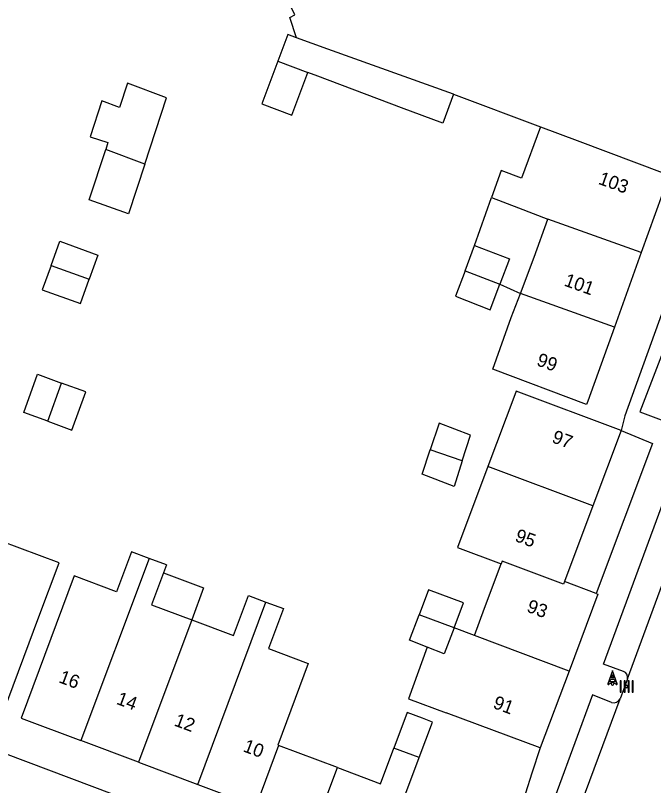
# Model space of a CAD drawing. Extents: x 192664 to 192925, y 446334 to 446521.
# Drawn here: x 192789.9 to 192837.8, y 446395.7 to 446453.5 of the extents above; entities that cross this region are included whole.
import ezdxf

# ---------------------------------------------------------------- set-up
doc = ezdxf.new("R2010")
doc.units = 0
for name, color, linetype in [('( Toegevoegd 29-11-2021 14_41_42) wegdeel vlak', 7, 'Continuous'), ('B-GV-KG-GRENS_WERKGRENS-G', 7, 'Continuous'), ('bovenleidingmast', 7, 'Continuous'), ('huisnummerreeks BGT', 7, 'Continuous'), ('kant open verharding', 7, 'Continuous'), ('kant verharding', 7, 'Continuous'), ('kolk', 7, 'Continuous'), ('Luifel', 7, 'Continuous'), ('pand op maaiveld vlak', 7, 'Continuous')]:
    doc.layers.add(name, color=color, linetype=linetype)

msp = doc.modelspace()

# ---------------------------------------------------------------- linework, layer by layer
at = {"layer": '( Toegevoegd 29-11-2021 14_41_42) wegdeel vlak'}
msp.add_lwpolyline([(192807.071, 446391.618), (192806.989, 446391.38), (192789.199, 446398.084), (192788.212, 446398.449), (192770.35, 446405.075), (192770.467, 446405.283)], dxfattribs=at)
at = {"layer": 'B-GV-KG-GRENS_WERKGRENS-G'}
msp.add_lwpolyline([(192845.78, 446436.459), (192844.328, 446436.785), (192842.142, 446437.586), (192836.819, 446423.746), (192840.619, 446422.317)], close=True, dxfattribs=at)
at = {"layer": 'bovenleidingmast'}
for p, q in [((192834.756, 446404.322), (192834.415, 446403.349)), ((192835.115, 446403.349), (192834.774, 446404.322))]:
    msp.add_line(p, q, dxfattribs=at)
msp.add_lwpolyline([(192834.887, 446403.699), (192834.957, 446403.499), (192834.573, 446403.499), (192834.643, 446403.699)], close=True, dxfattribs=at)
for points in [[(192834.774, 446404.019), (192834.852, 446403.799), (192834.678, 446403.799), (192834.756, 446404.019)], [(192834.509, 446403.316), (192834.538, 446403.399), (192834.678, 446403.399)], [(192834.852, 446403.399), (192834.992, 446403.399), (192835.021, 446403.316)]]:
    msp.add_lwpolyline(points, dxfattribs=at)
for centre, radius, start, end in [((192834.765, 446404.319), 0.01, 19.29005, 160.70995), ((192834.765, 446404.016), 0.01, 19.29005, 160.70995), ((192834.462, 446403.332), 0.05, 160.70995, 340.70995), ((192834.765, 446403.349), 0.1, 0, 180), ((192834.765, 446403.349), 0.1, 180, 0), ((192834.765, 446403.349), 0.1, 30, 150), ((192835.068, 446403.332), 0.05, 199.29005, 19.29005)]:
    msp.add_arc(centre, radius, start, end, dxfattribs=at)
at = {"layer": 'kant open verharding'}
for points in [[(192846.946, 446454.816), (192845.635, 446451.129), (192845.293, 446450.169), (192841.851, 446440.492), (192835.693, 446423.446), (192835.401, 446422.35)], [(192835.401, 446422.35), (192837.776, 446421.364), (192833.548, 446410.11)], [(192829.343, 446398.525), (192828.71, 446396.639), (192827.284, 446392.126)]]:
    msp.add_lwpolyline(points, dxfattribs=at)
at = {"layer": 'kant verharding'}
for p, q in [((192835.879, 446403.721), (192847.824, 446436.149)), ((192835.879, 446403.721), (192835.348, 446402.2)), ((192828.852, 446384.771), (192835.348, 446402.2))]:
    msp.add_line(p, q, dxfattribs=at)
for points in [[(192835.578, 446404.274), (192834.092, 446404.819), (192845.78, 446436.459), (192847.207, 446435.879)], [(192834.695, 446401.945), (192833.274, 446402.505), (192826.627, 446384.5)]]:
    msp.add_lwpolyline(points, dxfattribs=at)
for centre, radius, start, end in [((192835.451, 446403.846), 0.446, 343.69235, 73.42689), ((192834.859, 446402.489), 0.568, 253.24629, 329.41554)]:
    msp.add_arc(centre, radius, start, end, dxfattribs=at)
at = {"layer": 'kolk'}
for points in [[(192835.425, 446403.128), (192835.425, 446403.553), (192835.34, 446403.553), (192835.34, 446403.128), (192835.34, 446402.703), (192835.425, 446402.703)], [(192835.723, 446403.128), (192835.723, 446403.553), (192835.638, 446403.553), (192835.638, 446403.128), (192835.638, 446402.703), (192835.723, 446402.703)], [(192836.02, 446403.128), (192836.02, 446403.553), (192835.935, 446403.553), (192835.935, 446403.128), (192835.935, 446402.703), (192836.02, 446402.703)], [(192836.318, 446403.128), (192836.318, 446403.553), (192836.233, 446403.553), (192836.233, 446403.128), (192836.233, 446402.703), (192836.318, 446402.703)]]:
    msp.add_lwpolyline(points, close=True, dxfattribs=at)
for start, end in [(0, 180), (180, 0)]:
    msp.add_arc((192835.829, 446403.128), 0.1, start, end, dxfattribs=at)
at = {"layer": 'Luifel'}
for p, q in [((192824.406, 446436.208), (192825.677, 446439.814)), ((192826.303, 446433.31), (192827.856, 446432.619))]:
    msp.add_line(p, q, dxfattribs=at)
for points in [[(192809.636, 446450.044), (192808.434, 446446.847), (192810.703, 446445.994), (192811.905, 446449.19)], [(192801.06, 446411.669), (192804.079, 446410.539), (192803.18, 446408.138)]]:
    msp.add_lwpolyline(points, dxfattribs=at)
at = {"layer": 'pand op maaiveld vlak'}
for p, q in [((192809.636, 446450.044), (192811.905, 446449.19)), ((192822.832, 446447.565), (192829.348, 446445.115)), ((192799.655, 446442.322), (192796.727, 446443.426)), ((192836.921, 446435.689), (192829.917, 446438.195)), ((192823.695, 446434.314), (192824.406, 446436.208)), ((192836.921, 446435.689), (192834.902, 446430.082)), ((192792.626, 446434.715), (192795.486, 446433.679)), ((192823.695, 446434.314), (192826.303, 446433.31)), ((192834.902, 446430.082), (192827.856, 446432.619)), ((192792.379, 446423.035), (192793.415, 446425.895)), ((192835.401, 446422.35), (192833.275, 446416.68)), ((192823.485, 446420.072), (192821.091, 446420.878)), ((192833.275, 446416.68), (192825.41, 446419.628)), ((192833.275, 446416.68), (192831.149, 446411.009)), ((192799.989, 446412.75), (192794.873, 446399.08)), ((192801.283, 446412.266), (192799.989, 446412.75)), ((192801.283, 446412.266), (192801.06, 446411.669)), ((192833.548, 446410.11), (192831.149, 446411.009)), ((192803.639, 446395.798), (192808.756, 446409.467)), ((192803.18, 446408.138), (192799.184, 446397.466)), ((192822.87, 446407.533), (192820.248, 446408.501)), ((192824.402, 446406.959), (192822.87, 446407.533)), ((192831.506, 446404.294), (192824.402, 446406.959)), ((192831.506, 446404.294), (192829.343, 446398.525)), ((192829.343, 446398.525), (192822.281, 446401.173)), ((192799.184, 446397.466), (192794.873, 446399.08)), ((192809.693, 446398.714), (192807.995, 446394.168)), ((192814.113, 446397.059), (192809.693, 446398.714)), ((192820.25, 446397.804), (192818.344, 446398.518)), ((192819.25, 446395.133), (192820.25, 446397.804)), ((192799.184, 446397.466), (192803.639, 446395.798)), ((192811.461, 446389.974), (192814.113, 446397.059)), ((192803.639, 446395.798), (192807.995, 446394.168))]:
    msp.add_line(p, q, dxfattribs=at)
for points in [[(192811.054, 446451.801), (192810.545, 446453.32), (192810.916, 446453.523), (192809.437, 446456.628), (192809.575, 446456.694), (192822.797, 446462.99)], [(192811.054, 446451.801), (192810.39, 446452.051), (192809.636, 446450.044)], [(192822.832, 446447.565), (192813.388, 446450.95), (192811.054, 446451.801)], [(192822.832, 446447.565), (192822.026, 446445.384), (192818.939, 446446.545), (192812.653, 446448.909), (192811.905, 446449.19)], [(192799.655, 446442.322), (192801.281, 446447.288), (192798.356, 446448.4), (192797.756, 446446.568), (192796.436, 446447.059), (192795.568, 446444.366), (192796.895, 446443.939), (192796.727, 446443.426)], [(192829.348, 446445.115), (192827.942, 446441.255), (192826.414, 446441.835), (192825.677, 446439.814)], [(192829.348, 446445.115), (192832.102, 446444.08), (192838.693, 446441.612)], [(192799.655, 446442.322), (192798.431, 446438.581), (192795.483, 446439.628), (192796.727, 446443.426)], [(192838.693, 446441.612), (192839.008, 446441.484), (192836.921, 446435.689)], [(192825.677, 446439.814), (192827.703, 446439.028), (192829.917, 446438.195)], [(192827.856, 446432.619), (192828.885, 446435.328), (192829.917, 446438.195)], [(192792.626, 446434.715), (192793.291, 446436.532), (192796.147, 446435.486), (192795.486, 446433.679)], [(192824.406, 446436.208), (192827.023, 446435.225), (192826.303, 446433.31)], [(192792.626, 446434.715), (192791.961, 446432.898), (192794.824, 446431.871), (192795.486, 446433.679)], [(192823.695, 446434.314), (192822.984, 446432.42), (192825.584, 446431.396), (192826.303, 446433.31)], [(192834.902, 446430.082), (192832.903, 446424.53), (192832.816, 446424.287), (192825.772, 446426.935), (192827.165, 446430.802), (192827.856, 446432.619)], [(192792.379, 446423.035), (192790.572, 446423.697), (192791.598, 446426.56), (192793.415, 446425.895)], [(192792.379, 446423.035), (192794.187, 446422.374), (192795.233, 446425.23), (192793.415, 446425.895)], [(192835.401, 446422.35), (192827.536, 446425.299), (192827.428, 446425.012), (192825.41, 446419.628)], [(192823.485, 446420.072), (192824.099, 446421.995), (192821.766, 446422.885), (192821.091, 446420.878)], [(192823.485, 446420.072), (192822.871, 446418.149), (192820.479, 446419.062), (192821.091, 446420.878)], [(192825.41, 446419.628), (192823.139, 446413.572), (192826.405, 446412.347)], [(192784.643, 446402.882), (192789.06, 446401.234), (192791.717, 446408.352), (192793.234, 446412.413), (192788.818, 446414.063)], [(192799.989, 446412.75), (192798.667, 446413.245), (192797.546, 446410.249), (192794.37, 446411.438), (192790.374, 446400.764), (192794.873, 446399.08)], [(192824.402, 446406.959), (192825.155, 446409.014), (192826.405, 446412.347)], [(192831.149, 446411.009), (192831.077, 446410.816), (192826.477, 446412.54), (192826.405, 446412.347)], [(192801.06, 446411.669), (192800.161, 446409.268), (192803.18, 446408.138)], [(192803.18, 446408.138), (192806.327, 446406.96), (192807.448, 446409.956), (192808.756, 446409.467)], [(192822.87, 446407.533), (192823.576, 446409.412), (192820.959, 446410.395), (192820.248, 446408.501)], [(192833.548, 446410.11), (192833.67, 446410.064), (192831.506, 446404.294)], [(192808.756, 446409.467), (192810.064, 446408.977), (192808.942, 446405.98), (192811.931, 446404.861), (192809.638, 446398.734), (192809.693, 446398.714)], [(192820.861, 446406.086), (192819.537, 446406.607), (192820.248, 446408.501)], [(192822.87, 446407.533), (192822.138, 446405.583), (192820.861, 446406.086)], [(192820.861, 446406.086), (192819.442, 446402.214), (192822.281, 446401.173)], [(192820.25, 446397.804), (192821.249, 446400.473), (192820.502, 446400.752), (192819.343, 446401.186), (192818.344, 446398.518)], [(192814.113, 446397.059), (192817.345, 446395.849), (192818.344, 446398.518)]]:
    msp.add_lwpolyline(points, dxfattribs=at)

# ---------------------------------------------------------------- texts
at = {"layer": 'huisnummerreeks BGT'}
for s, rotation, p in [('103', 340.2, (192833.638, 446440.847)), ('101', 340.2, (192831.064, 446433.219)), ('99', 340.2, (192829.002, 446427.246)), ('97', 339.5, (192830.146, 446421.47)), ('95', 339.5, (192827.374, 446414.066)), ('93', 339.5, (192828.262, 446408.768)), ('16', 339.5, (192793.142, 446403.465)), ('14', 339.5, (192797.466, 446401.846)), ('91', 339.5, (192825.728, 446401.546)), ('12', 339.5, (192801.801, 446400.223)), ('10', 339.5, (192806.972, 446398.287))]:
    msp.add_text(s, height=1, rotation=rotation, dxfattribs=at).set_placement(p)

doc.saveas('drawing.dxf')
